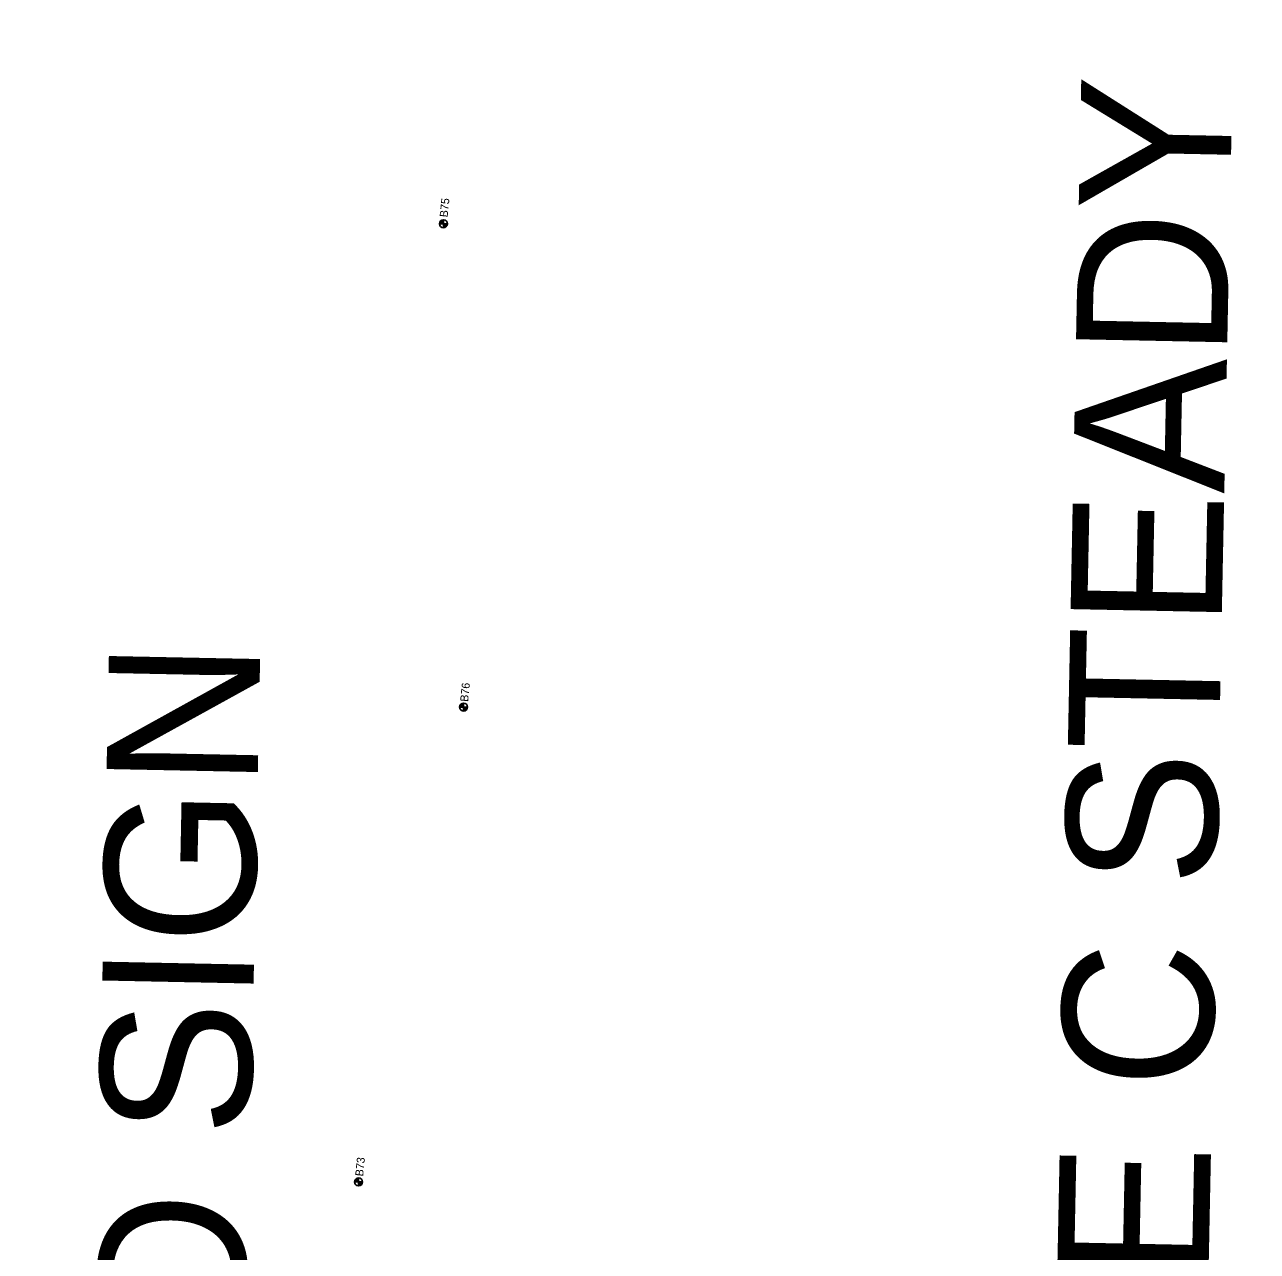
# Model space of a CAD drawing. Extents: x 345549 to 379569, y 127949 to 230467.
# Drawn here: x 359383 to 360923, y 171164 to 172696 of the extents above; entities that cross this region are included whole.
import ezdxf

# ---------------------------------------------------------------- set-up
doc = ezdxf.new("R2010")
doc.units = 0
for name, color, linetype in [('E_SOIL_BORE1 [KAPUR_CADDS_LEVELS]', 7, 'Continuous'), ('E_SOIL_BORE2 [KAPUR_CADDS_LEVELS]', 7, 'Continuous'), ('P_MARK', 7, 'Continuous'), ('P_TC_Text', 7, 'Continuous')]:
    doc.layers.add(name, color=color, linetype=linetype)

msp = doc.modelspace()

# ---------------------------------------------------------------- linework, layer by layer
at = {"layer": 'P_MARK'}
for p, q in [((359901.4, 172447.6), (359911.4, 172447.6)), ((359906.4, 172452.6), (359906.4, 172442.6)), ((359931.5, 171849), (359931.5, 171839)), ((359926.5, 171844), (359936.5, 171844)), ((359795.3, 171250.9), (359805.3, 171250.9)), ((359800.3, 171255.9), (359800.3, 171245.9))]:
    msp.add_line(p, q, dxfattribs=at)
for centre in [(359906.4, 172447.6), (359931.5, 171844), (359800.3, 171250.9)]:
    msp.add_circle(centre, 5, dxfattribs=at)
for centre, radius, start, end in [((359906.4, 172447.6), 4.5, 89.9869, 179.9869), ((359906.4, 172447.6), 4, 89.9869, 179.9869), ((359906.4, 172447.6), 3.5, 89.9869, 179.9869), ((359906.4, 172447.6), 3, 89.9869, 179.9869), ((359906.4, 172447.6), 2.5, 89.9869, 179.9869), ((359906.4, 172447.6), 2, 89.9869, 179.9869), ((359906.4, 172447.6), 1.5, 89.9869, 179.9869), ((359906.4, 172447.6), 1, 89.9869, 179.9869), ((359906.4, 172447.6), 0.5, 89.9869, 179.9869), ((359906.4, 172447.6), 4.5, 269.9869, 359.9869), ((359906.4, 172447.6), 4, 269.9869, 359.9869), ((359906.4, 172447.6), 3.5, 269.9869, 359.9869), ((359906.4, 172447.6), 3, 269.9869, 359.9869), ((359906.4, 172447.6), 2.5, 269.9869, 359.9869), ((359906.4, 172447.6), 2, 269.9869, 359.9869), ((359906.4, 172447.6), 1.5, 269.9869, 359.9869), ((359906.4, 172447.6), 1, 269.9869, 359.9869), ((359906.4, 172447.6), 0.5, 269.9869, 359.9869), ((359931.5, 171844), 4.5, 89.9869, 179.9869), ((359931.5, 171844), 4, 89.9869, 179.9869), ((359931.5, 171844), 3.5, 89.9869, 179.9869), ((359931.5, 171844), 3, 89.9869, 179.9869), ((359931.5, 171844), 2.5, 89.9869, 179.9869), ((359931.5, 171844), 2, 89.9869, 179.9869), ((359931.5, 171844), 1.5, 89.9869, 179.9869), ((359931.5, 171844), 1, 89.9869, 179.9869), ((359931.5, 171844), 0.5, 89.9869, 179.9869), ((359931.5, 171844), 4.5, 269.9869, 359.9869), ((359931.5, 171844), 4, 269.9869, 359.9869), ((359931.5, 171844), 3.5, 269.9869, 359.9869), ((359931.5, 171844), 3, 269.9869, 359.9869), ((359931.5, 171844), 2.5, 269.9869, 359.9869), ((359931.5, 171844), 2, 269.9869, 359.9869), ((359931.5, 171844), 1.5, 269.9869, 359.9869), ((359931.5, 171844), 1, 269.9869, 359.9869), ((359931.5, 171844), 0.5, 269.9869, 359.9869), ((359800.3, 171250.9), 4.5, 89.9869, 179.9869), ((359800.3, 171250.9), 4, 89.9869, 179.9869), ((359800.3, 171250.9), 3.5, 89.9869, 179.9869), ((359800.3, 171250.9), 3, 89.9869, 179.9869), ((359800.3, 171250.9), 2.5, 89.9869, 179.9869), ((359800.3, 171250.9), 2, 89.9869, 179.9869), ((359800.3, 171250.9), 1.5, 89.9869, 179.9869), ((359800.3, 171250.9), 1, 89.9869, 179.9869), ((359800.3, 171250.9), 0.5, 89.9869, 179.9869), ((359800.3, 171250.9), 4.5, 269.9869, 359.9869), ((359800.3, 171250.9), 4, 269.9869, 359.9869), ((359800.3, 171250.9), 3.5, 269.9869, 359.9869), ((359800.3, 171250.9), 3, 269.9869, 359.9869), ((359800.3, 171250.9), 2.5, 269.9869, 359.9869), ((359800.3, 171250.9), 2, 269.9869, 359.9869), ((359800.3, 171250.9), 1.5, 269.9869, 359.9869), ((359800.3, 171250.9), 1, 269.9869, 359.9869), ((359800.3, 171250.9), 0.5, 269.9869, 359.9869)]:
    msp.add_arc(centre, radius, start, end, dxfattribs=at)

# ---------------------------------------------------------------- texts
at = {"layer": 'E_SOIL_BORE1 [KAPUR_CADDS_LEVELS]'}
msp.add_text('B73', height=10, rotation=84.1728, dxfattribs=at).set_placement((359806, 171257.5))
at = {"layer": 'E_SOIL_BORE2 [KAPUR_CADDS_LEVELS]'}
for s, p in [('B75', (359911.5, 172455.4)), ('B76', (359937.1, 171850.2))]:
    msp.add_text(s, height=10, rotation=84.1728, dxfattribs=at).set_placement(p)
at = {"layer": 'P_TC_Text'}
for s, p in [('TRAFFIC CONTROL DRUM WITH TYPE C STEADY BURN LIGHT', (360771.8, 166649.6)), ('TYPE III BARRICADE WTH ATTACHED SIGN', (359572, 166673.8))]:
    msp.add_text(s, height=189, rotation=88.8462, dxfattribs=at).set_placement(p)

doc.saveas('drawing.dxf')
